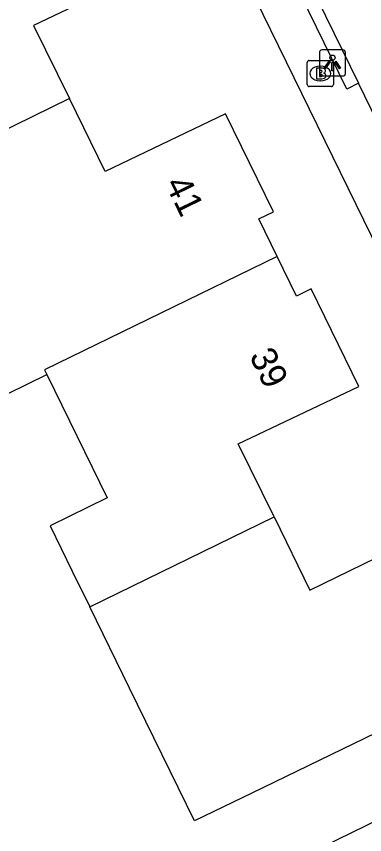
# Model space of a CAD drawing. Extents: x 160457 to 162082, y 388340 to 389736.
# Drawn here: x 160901.37 to 160914.74, y 388781.29 to 388812.73 of the extents above; entities that cross this region are included whole.
import ezdxf

# ---------------------------------------------------------------- set-up
doc = ezdxf.new("R2010")
doc.units = 0
for name, color, linetype in [('IMGEO_Brandkraan', 7, 'Continuous'), ('IMGEO_Lichtpunt', 7, 'Continuous'), ('IMGEO_Pand', 7, 'Continuous'), ('IMGEO_Pand_nummerreeks', 7, 'Continuous'), ('IMGEO_Voetpad_open', 7, 'Continuous')]:
    doc.layers.add(name, color=color, linetype=linetype)

msp = doc.modelspace()

# ---------------------------------------------------------------- linework, layer by layer
at = {"layer": 'IMGEO_Brandkraan'}
for p, q in [((160912.537, 388810.106), (160912.537, 388810.958)), ((160912.612, 388811.032), (160913.464, 388811.032)), ((160913.538, 388810.958), (160913.538, 388810.106)), ((160913.025, 388810.812), (160913.05, 388810.812)), ((160913.464, 388810.032), (160912.612, 388810.032)), ((160913.048, 388810.252), (160913.023, 388810.252))]:
    msp.add_line(p, q, dxfattribs=at)
for points in [[(160912.537, 388810.106), (160912.537, 388810.958)], [(160912.612, 388811.032), (160913.464, 388811.032)], [(160913.538, 388810.958), (160913.538, 388810.106)], [(160912.885, 388810.732), (160912.885, 388810.332), (160913.098, 388810.332)], [(160913.116, 388810.732), (160912.885, 388810.732)], [(160913.064, 388810.651), (160913.01, 388810.651), (160913.01, 388810.575)], [(160913.01, 388810.575), (160913.063, 388810.575)], [(160913.072, 388810.499), (160913.01, 388810.499), (160913.01, 388810.418)], [(160913.01, 388810.418), (160913.072, 388810.418)], [(160913.464, 388810.032), (160912.612, 388810.032)]]:
    msp.add_lwpolyline(points, dxfattribs=at)
for centre, radius, start, end in [((160912.614, 388810.956), 0.0765, 91.552, 178.448), ((160912.614, 388810.956), 0.0765, 91.552, 178.448), ((160913.462, 388810.956), 0.0765, 1.552, 88.448), ((160913.462, 388810.956), 0.0765, 1.552, 88.448), ((160913.065, 388810.613), 0.0379, 267.8285, 90.9355), ((160913.12, 388810.587), 0.145, 59.4692, 91.5367), ((160913.145, 388810.634), 0.0922, 285.5137, 58.1501), ((160913.073, 388810.458), 0.0404, 269.8759, 90.5077), ((160913.104, 388810.583), 0.251, 268.6676, 293.5347), ((160913.15, 388810.442), 0.105, 301.3115, 78.989), ((160912.614, 388810.108), 0.0765, 181.552, 268.448), ((160912.614, 388810.108), 0.0765, 181.552, 268.448), ((160913.462, 388810.108), 0.0765, 271.552, 358.448), ((160913.462, 388810.108), 0.0765, 271.552, 358.448)]:
    msp.add_arc(centre, radius, start, end, dxfattribs=at)
for centre, major_axis, ratio, start_param, end_param in [((160913.024, 388810.532), (-0.387, 0.002), 0.722429, 4.712389, 7.853982), ((160913.049, 388810.532), (-0.39, 0.002), 0.717154, 1.570796, 4.712389)]:
    msp.add_ellipse(centre, major_axis=major_axis, ratio=ratio, start_param=start_param, end_param=end_param, dxfattribs=at)
at = {"layer": 'IMGEO_Lichtpunt'}
for p, q in [((160913.004, 388811.341), (160913.004, 388810.534)), ((160913.004, 388811.341), (160913.004, 388810.534)), ((160913.906, 388811.436), (160913.098, 388811.436)), ((160913.906, 388811.436), (160913.098, 388811.436)), ((160914, 388810.534), (160914, 388811.341)), ((160914, 388810.534), (160914, 388811.341)), ((160913.098, 388810.44), (160913.906, 388810.44)), ((160913.098, 388810.44), (160913.906, 388810.44))]:
    msp.add_line(p, q, dxfattribs=at)
for points in [[(160913.378, 388811.005), (160913.417, 388810.977), (160913.229, 388810.715), (160913.191, 388810.742), (160913.378, 388811.005)], [(160913.48, 388810.957), (160913.527, 388810.957), (160913.527, 388810.635), (160913.48, 388810.635), (160913.48, 388810.957)], [(160913.59, 388810.977), (160913.628, 388811.004), (160913.815, 388810.742), (160913.776, 388810.714), (160913.59, 388810.977)]]:
    msp.add_lwpolyline(points, dxfattribs=at)
msp.add_circle((160913.503, 388811.139), 0.0994, dxfattribs=at)
for centre, start, end in [((160913.098, 388811.341), 90, 180), ((160913.098, 388811.341), 90, 180), ((160913.906, 388811.341), 0, 90), ((160913.906, 388811.341), 0, 90), ((160913.098, 388810.534), 180, 270), ((160913.098, 388810.534), 180, 270), ((160913.906, 388810.534), 270, 0), ((160913.906, 388810.534), 270, 360)]:
    msp.add_arc(centre, 0.0946, start, end, dxfattribs=at)
at = {"layer": 'IMGEO_Pand'}
for points in [[(160903.519, 388819.584), (160904.264, 388818.059), (160904.83, 388818.335), (160906.657, 388814.588), (160902.033, 388812.378), (160903.406, 388809.569)], [(160903.406, 388809.569), (160896.338, 388806.104)], [(160911.378, 388803.504), (160910.672, 388804.945), (160911.238, 388805.223), (160909.395, 388808.976), (160904.779, 388806.76), (160903.406, 388809.569)], [(160896.338, 388806.104), (160897.862, 388802.987), (160897.021, 388802.576), (160899.51, 388797.483), (160902.543, 388798.964)], [(160911.378, 388803.504), (160902.455, 388799.144), (160902.543, 388798.964)], [(160911.264, 388793.497), (160909.89, 388796.306), (160914.521, 388798.512), (160912.691, 388802.255), (160912.125, 388801.978), (160911.378, 388803.504)], [(160902.543, 388798.964), (160904.857, 388794.229), (160902.665, 388793.158), (160903.516, 388791.416), (160904.188, 388790.041)], [(160911.264, 388793.497), (160912.637, 388790.688), (160917.249, 388792.93), (160919.1, 388789.175), (160918.535, 388788.896), (160919.215, 388787.509), (160919.779, 388787.791), (160919.923, 388787.501), (160910.412, 388782.887), (160908.207, 388781.818), (160905.712, 388786.923), (160904.188, 388790.041)], [(160904.188, 388790.041), (160911.264, 388793.497)]]:
    msp.add_lwpolyline(points, dxfattribs=at)
at = {"layer": 'IMGEO_Voetpad_open'}
for points in [[(160923.043, 388787.867), (160881.086, 388873.64), (160879.017, 388877.835)], [(160914.506, 388810.154), (160914.057, 388809.935), (160910.561, 388817.082), (160911.01, 388817.301)], [(160911.01, 388817.301), (160914.506, 388810.154)], [(160918.424, 388802.124), (160914.506, 388810.154)], [(160875.947, 388762.656), (160922.127, 388785.223)]]:
    msp.add_lwpolyline(points, dxfattribs=at)

# ---------------------------------------------------------------- texts
at = {"layer": 'IMGEO_Pand_nummerreeks'}
for s, rotation, p in [('41', 296.1553, (160907.058, 388806.294)), ('39', 296.0522, (160910.297, 388799.685))]:
    msp.add_text(s, height=1, rotation=rotation, dxfattribs=at).set_placement(p)

doc.saveas('drawing.dxf')
